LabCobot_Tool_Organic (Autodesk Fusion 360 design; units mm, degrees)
sketch "Skizze13" plane through (0, 0, 0) normal (0, 0, 1) x axis (1, 0, 0)
  circle C1 centre (0, 0) radius 37.5
  point P1 (0, 0)
  point P2 (0, 0)
  coincident P1 P2
  dimension "d69" diameter C1 = 75
extrude "Extrusion14" new body sketch "Skizze13" along normal blind 80
sketch "Skizze16" plane through (0, 0, 0) normal (0, 0, 1) x axis (1, 0, 0)
  circle C1 centre (0, 0) radius 31.5
  circle C2 centre (-31.5, 0) radius 3.3
  circle C3 centre (31.5, 0) radius 3.3
  point P1 (0, 0)
  point P2 (0, 0)
  point P3 (-31.5, 0)
  point P4 (31.5, 0)
  coincident P1 P2
  coincident C1 P3
  coincident C1 P4
  dimension "d79" diameter C1 = 63
  dimension "d80" diameter C2 = 6.6
  dimension "d81" diameter C3 = 6.6
extrude "Extrusion15" cut sketch "Skizze16" along normal blind 10
work_plane "Arbeitsebene2" AlongDistance 37.5
sketch "Skizze18" plane through (0, 37.5, 0) normal (0, 1, 0) x axis (1, 0, 0)
  line L1 (-47.5, -46.7371) -> (47.5, -46.7371)
  line L2 (-47.5, -16.7371) -> (-47.5, -46.7371)
  line L3 (47.5, -16.7371) -> (-47.5, -16.7371)
  line L4 (47.5, -46.7371) -> (47.5, -16.7371)
  line L5 (0, -16.7371) -> (0, -46.7371)
  line L6 (0, 0) -> (0, -100)
  point P6 (0, -46.7371)
  point P7 (0, -16.7371)
  point P1 (0, 0)
  point P9 (0, 0)
  point P2 (47.5, -46.7371)
  point P5 (47.5, -16.7371)
  point P3 (-47.5, -46.7371)
  horizontal L1
  vertical L2
  horizontal L3
  vertical L4
  coincident L1 P6
  coincident L3 P7
  perpendicular L3 L5
  coincident P1 P9
  vertical L6
  collinear L5 L6
  dimension "d85" distance P2 P5 = 30
  dimension "d86" distance P2 P3 = 95
  dimension "d87" distance L2 L5 = 47.5
work_plane "Arbeitsebene3" AlongDistance 37.5
sketch "Skizze20" plane through (37.5, 0, 0) normal (1, 0, 0) x axis (0, 1, 0)
  line L1 (-37.5, 80.1293) -> (0, 80.1293)
  line L2 (-37.5, 0.1293) -> (-37.5, 80.1293)
  line L3 (0, 0.1293) -> (-37.5, 0.1293)
  line L4 (0, 80.1293) -> (0, 0.1293)
  line L5 (37.5, 80.1293) -> (0, 80.1293)
  line L6 (37.5, 0.1293) -> (37.5, 80.1293)
  line L7 (0, 0.1293) -> (37.5, 0.1293)
  line L8 (0, 80.1293) -> (0, 0.1293)
  line L9 (-37.5, 52.2905) -> (37.5, 80.1293)
  line L10 (37.5, 80.1293) -> (-37.5, 80.1293)
  line L11 (-37.5, 80.1293) -> (-37.5, 52.2905)
  point P9 (-37.5, 52.2905)
  point P2 (0, 80.1293)
  point P5 (0, 0.1293)
  point P3 (-37.5, 80.1293)
  point P6 (37.5, 80.1293)
  point P7 (37.5, 0.1293)
  horizontal L1
  vertical L2
  horizontal L3
  vertical L4
  horizontal L5
  vertical L6
  horizontal L7
  vertical L8
  coincident L2 P9
  dimension "d92" distance P2 P5 = 80
  dimension "d93" distance P2 P3 = 37.5
  dimension "d94" distance P2 P6 = 37.5
  dimension "d95" distance P6 P7 = 80
  dimension "d96" distance P6 P9 = 80
extrude "Extrusion16" cut sketch "Skizze20" profile of L1 L2 L4 L5 L8 L9 L10 L11 against normal blind 80
sketch "Skizze22" plane through (0, -21.6001, 58.1923) normal (0, -0.348, 0.9375) x axis (1, 0, 0)
  line L1 (31.5, 25) -> (0, 25)
  line L2 (-31.5, 25) -> (0, 25)
  line L3 (-5.1003, 62.6684) -> (5.1003, 62.6684)
  circle C1 centre (0, 25) radius 31.5
  circle C2 centre (-31.5, 25) radius 3.35
  circle C3 centre (31.5, 25) radius 3.35
  closed curve K1 centre (0, 23.0401)
  point P2 (0, 25)
  point P3 (0, 25)
  point P4 (31.5, 25)
  point P5 (0, 25)
  point P6 (-31.5, 25)
  point P7 (-31.5, 25)
  point P8 (31.5, 25)
  coincident P2 P3
  coincident C1 P4
  horizontal L1
  coincident P2 P5
  coincident C1 P6
  parallel L1 L2
  coincident P6 P7
  coincident P4 P8
  dimension "d99" diameter C1 = 63
  dimension "d100" diameter C2 = 6.7
  dimension "d101" diameter C3 = 6.7
extrude "Extrusion17" cut sketch "Skizze22" profile of C1 L1 L2 C2 C3 along a picked direction blind -10
extrude "Extrusion18" add sketch "Skizze18" against normal blind 75
sketch "Skizze23" plane through (0, -21.6001, 58.1923) normal (0, -0.348, 0.9375) x axis (1, 0, 0)
  line L1 (-5.1003, 62.6684) -> (5.1003, 62.6684)
  closed curve K1 centre (0, 23.0401)
  circle C1 centre (31.5, 25) radius 3.35
  circle C2 centre (-31.5, 25) radius 3.35
sketch "Skizze24" plane through (47.5, 0, 0) normal (1, 0, 0) x axis (0, 1, 0)
  line L1 (37.5, 46.7371) -> (37.5, 16.7371)
  line L2 (-37.5, 46.7371) -> (37.5, 46.7371)
  line L3 (-37.5, 16.7371) -> (-37.5, 46.7371)
  line L4 (37.5, 16.7371) -> (-37.5, 16.7371)
  line L5 (-36.7, 18.7371) -> (-37.5, 18.7371)
  line L6 (-36.7, 18.1871) -> (-36.7, 18.7371)
  line L7 (-21.5, 17.7371) -> (-36.7, 18.1871)
  line L8 (-21.5, 45.7371) -> (-21.5, 17.7371)
  line L9 (-36.7, 46.2871) -> (-21.5, 45.7371)
  line L10 (-36.7, 45.7371) -> (-36.7, 46.2871)
  line L11 (-37.5, 45.7371) -> (-36.7, 45.7371)
  line L12 (-37.5, 18.7371) -> (-37.5, 45.7371)
  point P6 (-37.5, 18.7371)
  point P13 (-37.5, 45.7371)
  point P9 (-21.5, 17.7371)
  point P10 (-21.5, 45.7371)
  point P8 (-36.7, 18.1871)
  point P11 (-36.7, 46.2871)
  point P12 (-36.7, 45.7371)
  coincident L3 P6
  perpendicular L3 L5
  perpendicular L5 L6
  perpendicular L5 L8
  coincident L3 P13
  perpendicular L3 L11
  equal L6 L10
  parallel L10 L12
  parallel L6 L12
  equal L5 L11
  dimension "d106" distance P9 P10 = 28
  dimension "d108" distance P8 P11 = 28.1
  dimension "d109" distance L5 L11 = 27
  dimension "d110" distance P12 P13 = 0.8
  dimension "d111" distance L8 L12 = 16
  dimension "d112" distance L2 L11 = 1
  dimension "d113" distance L2 P10 = 1
extrude "Extrusion19" cut sketch "Skizze24" profile of L3 L5 L6 L7 L8 L9 L10 L11 L12 against normal blind 95
sketch "Skizze25" plane through (0, -21.5, 0) normal (0, -1, 0) x axis (1, 0, 0)
  line L1 (47.5, 45.7371) -> (47.5, 17.7371)
  line L2 (-47.5, 45.7371) -> (47.5, 45.7371)
  line L3 (-47.5, 17.7371) -> (-47.5, 45.7371)
  line L4 (47.5, 17.7371) -> (-47.5, 17.7371)
  line L5 (41.5, 45.7371) -> (-41.5, 45.7371)
  line L6 (41.5, 17.7371) -> (41.5, 45.7371)
  line L7 (-41.5, 17.7371) -> (41.5, 17.7371)
  line L8 (-41.5, 45.7371) -> (-41.5, 17.7371)
  line L9 (0, 17.7371) -> (0, 45.7371)
  point P8 (41.5, 17.7371)
  point P6 (-41.5, 45.7371)
  point P10 (0, 45.7371)
  point P11 (0, 17.7371)
  point P7 (41.5, 45.7371)
  horizontal L5
  vertical L6
  horizontal L7
  vertical L8
  coincident L4 P8
  coincident L2 P6
  midpoint L2 P10
  midpoint L4 P11
  dimension "d116" distance P6 P7 = 83
  dimension "d117" distance L8 L9 = 41.5
extrude "Extrusion20" cut sketch "Skizze25" profile of L2 L4 L5 L6 L7 L8 L9 against normal blind 5
sketch "Skizze26" plane through (-47.5, 0, 0) normal (-1, 0, 0) x axis (0, -1, 0)
  line L1 (37.5, 45.7371) -> (36.7, 45.7371)
  line L2 (37.5, 46.7371) -> (37.5, 45.7371)
  line L3 (-37.5, 46.7371) -> (37.5, 46.7371)
  line L4 (-37.5, 16.7371) -> (-37.5, 46.7371)
  line L5 (37.5, 16.7371) -> (-37.5, 16.7371)
  line L6 (37.5, 18.7371) -> (37.5, 16.7371)
  line L7 (36.7, 18.7371) -> (37.5, 18.7371)
  line L8 (36.7, 18.1871) -> (36.7, 18.7371)
  line L9 (21.5, 17.7371) -> (36.7, 18.1871)
  line L10 (21.5, 45.7371) -> (21.5, 17.7371)
  line L11 (36.7, 46.2871) -> (21.5, 45.7371)
  line L12 (36.7, 45.7371) -> (36.7, 46.2871)
  line L13 (37.5, 54.7371) -> (-37.5, 54.7371)
  line L14 (37.5, 8) -> (37.5, 54.7371)
  line L15 (-37.5, 8) -> (37.5, 8)
  line L16 (-37.5, 54.7371) -> (-37.5, 8)
  line L17 (-37.5, 0) -> (37.5, 0)
  horizontal L13
  vertical L14
  horizontal L15
  vertical L16
  collinear L6 L14
  collinear L4 L16
  dimension "d124" distance L15 L17 = 8
  dimension "d125" distance L3 L13 = 8
extrude "Extrusion21" cut sketch "Skizze26" profile of L1 L2 L3 L4 L5 L6 L7 L8 L9 L10 L11 L12 L13 L14 L15 L16 against normal blind 25
extrude "Extrusion22" cut sketch "Skizze23" profile of C2 against normal blind 18
sketch "Skizze27" plane through (47.5, 0, 0) normal (1, 0, 0) x axis (0, 1, 0)
  line L1 (-36.7, 45.7371) -> (-37.5, 45.7371)
  line L2 (-36.7, 46.2871) -> (-36.7, 45.7371)
  line L3 (-21.5, 45.7371) -> (-36.7, 46.2871)
  line L4 (-21.5, 17.7371) -> (-21.5, 45.7371)
  line L5 (-36.7, 18.1871) -> (-21.5, 17.7371)
  line L6 (-36.7, 18.7371) -> (-36.7, 18.1871)
  line L7 (-37.5, 18.7371) -> (-36.7, 18.7371)
  line L8 (-37.5, 16.7371) -> (-37.5, 18.7371)
  line L9 (37.5, 16.7371) -> (-37.5, 16.7371)
  line L10 (37.5, 46.7371) -> (37.5, 16.7371)
  line L11 (-37.5, 46.7371) -> (37.5, 46.7371)
  line L12 (-37.5, 45.7371) -> (-37.5, 46.7371)
sketch "Skizze28" plane through (47.5, 0, 0) normal (1, 0, 0) x axis (0, 1, 0)
  line L1 (37.5, 8) -> (-37.5, 8)
  line L2 (37.5, 54.7371) -> (37.5, 8)
  line L3 (-37.5, 54.7371) -> (37.5, 54.7371)
  line L4 (-37.5, 8) -> (-37.5, 54.7371)
  line L5 (-37.5, 0) -> (37.5, 0)
  line L6 (-37.5, 46.7371) -> (37.5, 46.7371)
  line L7 (-37.5, 16.7371) -> (-37.5, 18.7371)
  line L8 (37.5, 46.7371) -> (37.5, 16.7371)
  horizontal L1
  vertical L2
  horizontal L3
  vertical L4
  collinear L4 L7
  collinear L2 L8
  dimension "d126" distance L1 L5 = 8
  dimension "d127" distance L3 L6 = 8
extrude "Extrusion23" cut sketch "Skizze27" + "Skizze28" profile of S1:L1 S1:L2 S1:L3 S1:L4 S1:L5 S1:L6 S1:L7 S1:L8 S1:L9 S1:L10 S1:L11 S1:L12 S2:L1 S2:L2 S2:L3 S2:L4 S2:L6 S2:L7 S2:L8 blind -25
work_plane "Arbeitsebene4" AlongDistance -37.5
sketch "Skizze29" plane through (-37.5, 0, 0) normal (1, 0, 0) x axis (0, 1, 0)
  line L1 (-37.5, 52.2905) -> (37.1515, 80)
  line L2 (37.1515, 52.2905) -> (37.1515, 80)
  line L3 (-37.5, 52.2905) -> (37.1515, 52.2905)
  line L4 (37.1515, 80) -> (-37.5, 52.2905)
  line L5 (-9.6623, 54.0901) -> (37.2283, 71.4952)
  line L6 (37.2283, 54.0901) -> (-9.6623, 54.0901)
  line L7 (37.2283, 71.4952) -> (37.2283, 54.0901)
  point P4 (37.1515, 80)
  point P5 (37.1515, 80)
  point P3 (-37.5, 52.2905)
  point P6 (-37.5, 52.2905)
  vertical L2
  perpendicular L2 L3
  coincident P4 P5
  coincident P3 P6
  parallel L1 L5
  horizontal L6
  perpendicular L6 L7
  dimension "d132" distance L1 L5 = 8
extrude "Extrusion24" cut sketch "Skizze29" profile of L2 L5 L6 along normal blind 15
fillet "Abrundung10" radius 10
work_plane "Arbeitsebene5" AlongDistance 37.5
sketch "Skizze30" plane through (37.5, 0, 0) normal (1, 0, 0) x axis (0, 1, 0)
  line L1 (37.4612, 80.3016) -> (-37.4027, 52.3111)
  line L2 (37.4612, 52.3111) -> (37.4612, 80.3016)
  line L3 (-37.4027, 52.3111) -> (37.4612, 52.3111)
  line L4 (45.4971, 74.7652) -> (-14.5591, 52.3111)
  line L5 (45.4971, 52.3111) -> (45.4971, 74.7652)
  line L6 (45.4971, 52.3111) -> (-14.5591, 52.3111)
  vertical L2
  perpendicular L2 L3
  vertical L5
  parallel L3 L6
  parallel L1 L4
  collinear L3 L6
  dimension "d138" distance L1 L4 = 8
  dimension "d139" angle L1 L3 = 20.5
extrude "Extrusion25" cut sketch "Skizze30" profile of L2 L3 L4 L5 L6 against normal blind 15
fillet "Abrundung11" radius 10
sketch "Skizze31" plane through (-22.5, 0, 0) normal (-1, 0, 0) x axis (0, -1, 0)
  line L1 (7.9193, 44.7371) -> (16.5, 44.7371)
  line L2 (-30, 68.8121) -> (-1.4557, 58.2169)
  line L3 (-30, 46.7371) -> (-30, 68.8121)
  line L4 (-37.5, 46.7371) -> (-30, 46.7371)
  line L5 (-37.5, 16.7371) -> (-37.5, 46.7371)
  line L6 (-30, 16.7371) -> (-37.5, 16.7371)
  line L7 (-30, 8) -> (-30, 16.7371)
  line L8 (30, 8) -> (-30, 8)
  line L9 (30, 16.7371) -> (30, 8)
  line L10 (37.5, 16.7371) -> (30, 16.7371)
  line L11 (37.5, 18.7371) -> (37.5, 16.7371)
  line L12 (36.7, 18.7371) -> (37.5, 18.7371)
  line L13 (36.7, 18.1871) -> (36.7, 18.7371)
  line L14 (21.5, 17.7371) -> (36.7, 18.1871)
  line L15 (16.5, 17.7371) -> (21.5, 17.7371)
  line L16 (16.5, 44.7371) -> (16.5, 17.7371)
  line L17 (11.5, 17.7371) -> (16.5, 17.7371)
  line L18 (11.5, 44.7371) -> (11.5, 17.7371)
  line L19 (16.5, 44.7371) -> (11.5, 44.7371)
  line L20 (16.5, 17.7371) -> (16.5, 44.7371)
  arc A1 centre (7.9193, 54.7371) radius 10 clockwise from (7.9193, 44.7371) to (-1.4557, 58.2169)
  point P19 (16.5, 17.7371)
  point P20 (16.5, 17.7371)
  horizontal L17
  vertical L18
  horizontal L19
  vertical L20
  coincident P19 P20
  dimension "d144" distance L18 L20 = 5
  dimension "d145" distance L17 L19 = 27
extrude "Extrusion26" add sketch "Skizze31" profile of L16 L17 L18 L19 L20 along normal blind 15
extrude "Extrusion33" add sketch "Skizze31" profile of L1 L16 L17 L18 L19 L20 along normal blind 22.5
sketch "Skizze37" plane through (0, -16.5, 0) normal (0, -1, 0) x axis (1, 0, 0)
  line L1 (22.5, 17.7371) -> (-22.5, 17.7371)
  line L2 (22.5, 44.7371) -> (22.5, 17.7371)
  line L3 (-22.5501, 45.7371) -> (22.5501, 45.7371)
  line L4 (-45, 44.7371) -> (-22.5, 44.7371)
  line L5 (-45, 17.7371) -> (-45, 44.7371)
  line L6 (-22.5, 17.7371) -> (-45, 17.7371)
  line L7 (0, 44.7371) -> (-45, 44.7371)
  line L8 (0, 17.7371) -> (0, 44.7371)
  line L9 (-45, 17.7371) -> (0, 17.7371)
  line L10 (-45, 44.7371) -> (-45, 17.7371)
  arc A1 centre (32.5, 44.7371) radius 10 clockwise from (22.5, 44.7371) to (22.5501, 45.7371)
  arc A2 centre (-32.5, 44.7371) radius 10 clockwise from (-22.5501, 45.7371) to (-22.5, 44.7371)
  circle C1 centre (-37, 35.7371) radius 3.3
  point P14 (0, 17.7371)
  point P10 (-45, 44.7371)
  point P12 (-45, 44.7371)
  point P16 (-37, 35.7371)
  horizontal L7
  vertical L8
  horizontal L9
  vertical L10
  midpoint L1 P14
  coincident P10 P12
  dimension "d174" diameter C1 = 6.6
  dimension "d175" distance L7 P16 = 9
  dimension "d176" distance L10 P16 = 8
extrude "Extrusion34" cut sketch "Skizze37" profile of C1 against normal blind 7
sketch "Skizze38" plane through (-45, 0, 0) normal (-1, 0, 0) x axis (0, -1, 0)
  line L1 (11.5, 44.7371) -> (16.5, 44.7371)
  line L2 (11.5, 17.7371) -> (11.5, 44.7371)
  line L3 (16.5, 17.7371) -> (11.5, 17.7371)
  line L4 (16.5, 44.7371) -> (16.5, 17.7371)
  line L5 (39.8827, 19.9414) -> (16.5, 19.9414)
  line L6 (39.8827, 5.9414) -> (39.8827, 19.9414)
  line L7 (16.5, 5.9414) -> (39.8827, 5.9414)
  line L8 (16.5, 19.9414) -> (16.5, 5.9414)
  point P6 (16.5, 19.9414)
  point P9 (16.5, 5.9414)
  horizontal L5
  vertical L6
  horizontal L7
  vertical L8
  coincident L4 P6
  dimension "d179" distance P6 P9 = 14
extrude "Extrusion35" cut sketch "Skizze38" profile of L4 L5 L6 L7 L8 against normal blind 45
fillet "Abrundung15" radius 31.5
fillet "Abrundung16" radius 6
fillet "Abrundung17" radius 10.5
fillet "Abrundung18" radius 5
fillet "Abrundung19" radius 2
extrude "Extrusion27" cut blind -17
fillet "Abrundung12" radius 2.5
sketch "Skizze33" plane through (-22.5, 0, 0) normal (-1, 0, 0) x axis (0, -1, 0)
  line L1 (11.5, 44.7371) -> (11.5, 8)
  line L2 (7.9193, 44.7371) -> (11.5, 44.7371)
  line L3 (-30, 68.8121) -> (-1.4557, 58.2169)
  line L4 (-30, 46.7371) -> (-30, 68.8121)
  line L5 (-37.5, 46.7371) -> (-30, 46.7371)
  line L6 (-37.5, 16.7371) -> (-37.5, 46.7371)
  line L7 (-30, 16.7371) -> (-37.5, 16.7371)
  line L8 (-30, 8) -> (-30, 16.7371)
  line L9 (11.5, 8) -> (-30, 8)
  line L10 (32.1209, 8) -> (32.1209, 18.0515)
  line L11 (17.5, 8) -> (32.1209, 8)
  line L12 (17.5, 17.7371) -> (17.5, 8)
  line L13 (17.5, 17.7371) -> (32.1209, 18.0515)
  arc A1 centre (7.9193, 54.7371) radius 10 clockwise from (7.9193, 44.7371) to (-1.4557, 58.2169)
  point P16 (17.5, 8)
  vertical L10
  horizontal L11
  coincident L9 P16
extrude "Extrusion28" cut sketch "Skizze33" profile of L9 L10 L11 against normal blind 20
extrude "Extrusion29" cut sketch "Skizze33" profile of L9 L10 L11 L12 L13 against normal blind 20
fillet "Abrundung13" radius 10
fillet "Abrundung14" radius 10
extrude "Extrusion30" add sketch "Skizze31" profile of L1 L16 L17 L18 L19 L20 along normal blind 19
extrude "Extrusion32" add sketch "Skizze31" profile of L1 L16 L17 L18 L19 L20 along normal blind 22.5
extrude "Extrusion31" add sketch "Skizze31" profile of L1 L16 L17 L18 L19 L20 along normal blind 22.5
extrude "Extrusion36" cut sketch "Skizze37" profile of C1 against normal blind 7
sketch "Skizze65" plane through (0, 0, 0) normal (0, 1, 0) x axis (1, 0, 0)
  line L1 (46, -44.7) -> (22.5, -44.7)
  line L2 (46, -8) -> (46, -44.7)
  line L3 (22.5, -8) -> (46, -8)
  arc A1 centre (50.3611, -26.35) radius 33.3611 clockwise from (22.5, -44.7) to (22.5, -8)
extrude "Extrusion58" new body sketch "Skizze65" along normal blind 40 and against normal blind 16.5 bodies "TOOL_waist_pX"
sketch "Skizze66" plane through (0, 0, 0) normal (0, 1, 0) x axis (1, 0, 0)
  line L1 (-46, -8) -> (-22.5, -8)
  line L2 (-46, -44.7) -> (-46, -8)
  line L3 (-22.5, -44.7) -> (-46, -44.7)
  arc A1 centre (-50.3611, -26.35) radius 33.3611 clockwise from (-22.5, -8) to (-22.5, -44.7)
extrude "Extrusion59" new body sketch "Skizze66" along normal blind 40 and against normal blind 11.5 bodies "TOOL_waist_nX"
sketch "Skizze67" plane through (0, 0, 0) normal (1, 0, 0) x axis (0, 0, -1)
  line L1 (-16.7, 46) -> (-16.7, 37.5)
  line L2 (-46, 46) -> (-16.7, 46)
  line L3 (-46, 37.5) -> (-46, 46)
  arc A1 centre (-31.35, 56.45) radius 23.9526 clockwise from (-16.7, 37.5) to (-46, 37.5)
extrude "Extrusion60" new body sketch "Skizze67" distance 54 bodies "TOOL_waist_rear"
work_plane "Arbeitsebene23" AlongDistance 16 ExtraOffset 0
sketch "Skizze68" plane through (0, 16, 0) normal (0, 1, 0) x axis (1, 0, 0)
  curve K1 (15, -54) -> (-15, -54)
  line L1 (-15, -54) -> (15, -54)
extrude "Extrusion61" new body sketch "Skizze68" distance 48 bodies "TOOL_fork"
combine "Kombinieren" bodies "TOOL_waist_pX", "TOOL_waist_nX", "TOOL_waist_rear", "TOOL_fork"
fillet "Abrundung149" StartRadius 8 EndRadius 1 MidRadius 3 MidRadius 8.5 MidRadius 8 MidRadius 4 MidParams 0.354 MidParams 0.55 MidParams 0.75 MidParams 0.9
fillet "Abrundung150" StartRadius 8 EndRadius 1 MidRadius 3 MidRadius 8.5 MidRadius 8 MidRadius 4 MidParams 0.277 MidParams 0.5 MidParams 0.75 MidParams 0.9
fillet "Abrundung151" radius 14
fillet "Abrundung152" radius 14
fillet "Abrundung153" radius 7
fillet "Abrundung154" radius 6
fillet "Abrundung155" radius 5
fillet "Abrundung156" radius 5
fillet "Abrundung157" radius 8
fillet "Abrundung158" radius 8
fillet "Abrundung159" radius 2.5
fillet "Abrundung160" radius 2.5
fillet "Abrundung161" radius 1.5
fillet "Abrundung162" radius 2.5
fillet "Abrundung163" radius 2.5
fillet "Abrundung164" radius 2.5
fillet "Abrundung165" radius 2.5
fillet "Abrundung166" radius 2.5
fillet "Abrundung167" radius 2.5
fillet "Abrundung168" radius 1.5
fillet "Abrundung169" radius 2.5
fillet "Abrundung170" radius 1.5
fillet "Abrundung171" radius 2.5
fillet "Abrundung172" radius 2.5
fillet "Abrundung173" radius 2.5
fillet "Abrundung174" radius 2.5
fillet "Abrundung175" radius 2.5
fillet "Abrundung176" radius 2.5
fillet "Abrundung177" radius 2.5
fillet "Abrundung178" radius 2.5
fillet "Abrundung179" radius 2.5
fillet "Abrundung180" radius 2.5
fillet "Abrundung181" radius 2.5
fillet "Abrundung182" radius 2.5
fillet "Abrundung183" radius 1.5
fillet "Abrundung184" radius 2.5
fillet "Abrundung185" radius 2.5
fillet "Abrundung186" radius 1.5
fillet "Abrundung187" radius 2.5
fillet "Abrundung188" radius 2.5
fillet "Abrundung189" radius 2.5
fillet "Abrundung190" radius 2.5
fillet "Abrundung191" radius 2.5
fillet "Abrundung192" radius 2.5
fillet "Abrundung193" radius 2.5
fillet "Abrundung194" radius 2.5
fillet "Abrundung195" radius 2.5
fillet "Abrundung196" radius 2.5
fillet "Abrundung197" radius 2.5
fillet "Abrundung198" radius 2.5
fillet "Abrundung199" radius 2.5
fillet "Abrundung200" radius 2.5
fillet "Abrundung201" radius 2.5
fillet "Abrundung202" radius 2.5
chamfer "Fase6" distance 0.8
chamfer "Fase7" distance 0.6
chamfer "Fase8" distance 0.6
named bodies: "TOOL_waist_pX", "TOOL_waist_nX", "TOOL_waist_rear", "TOOL_fork"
